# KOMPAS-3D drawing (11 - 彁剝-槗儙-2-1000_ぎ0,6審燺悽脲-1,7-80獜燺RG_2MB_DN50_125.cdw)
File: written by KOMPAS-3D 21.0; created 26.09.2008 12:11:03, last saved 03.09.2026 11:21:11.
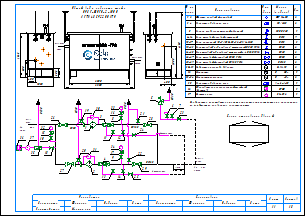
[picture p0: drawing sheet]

Sheets 1-2: A3, landscape

Document properties: Наименование: Макро:21; Автор: RaskoAdmin; Форматы листов документа: 2xA3; Полное имя файла: \\UR38nt01\Departments\КТО\КБ ПУРДГ\Заявки\Прайс-лист на типовые шкафы ГРПШ\ПРДГ_стандарт_20_03_2026\ПРДГ с RG_2MB\ПРДГ-ШУГО-2-1000_до0,6МПа_Рвых-1,7-80кПа_RG_2MB_DN50_125.cdw

Title block, sheet 1: Наименование: Пункт учета газа / ПУГ-Ш-400-Р / ЛГТИ.485922.001ТУ; designation: ЛГТИ.03.4411141; sheet number: 1; Количество листов документа: 2; organisation: ООО "ЭЛЬСТЕР Газэлектроника"; Форматы листов документа: A3; stored path: C:\Рабочие документы\Компас\ПУГ\Схема.cdw; Разработал: Устинов; Проверил: Кошкин; Утвердил: Кошкин
Title block, sheet 2: sheet number: 2; stored path: D:\Рабочие документы\Заявки\ПУРДГ\ПУРДГ-ШУЭО-2-100-Р 4411220.cdw; designation, second copy: ЛГТИ.03.4411141-

Views: Вид 1, Вид 2
Referenced files: wcvoit.frw
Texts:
  Normal
  Вход
  газа
  PDI
  Выход
  Р=     кПа
  DN125
  DN50
  DN20
  Импульс DN20
  ≥5DN
  HYSWLongFangSong
  Общий вид и габариты шкафа
  ПРДГ-ШУГО-2-1000
  Выход газа
  Вход газа
  Р=        МПа
  logo-rasko-ge.png
  № на
  схеме
  Усл.
  обозн.
  Марка
  (модель)
  Кол.
  Фильтр газовый фланцевый
  ФГ 16-50
  Регулятор давления газа
  RG/2MB
  Клапан предохранительный сбросной
  КПС DN20
  Кран шаровой газовый латунный
  DN15
  Кран кнопочный VE-РАСКО-НЗ-1,6-G1/2-М20
  Кран шаровой "под приварку" штуцерный DN20 PN16
  Кран шаровой "под приварку" штуцерный п/п DN20 PN16
  Кран шаровой фланцевый DN50 PN16
  Кран шаровой фланцевый DN125 PN16
  Индикатор перепада давления
  Delta 15
  Манометр
  Манометр-напоромер
  0...     МПа
  0...     кПа
  Обогреватель газогорелочный шкафной
  (Эльтон")
  Счетчик газа
  Venio-A-15
  ОГШН
  BK-G1,6
  Схема открывания дверей
  Предприятие изготовитель может заменять комплектующие на аналогичные,
  не ухудшающие заявленных характеристик.
  Должность
  Конструктор
  Фамилия
  Подпись
  Дата
  Согласовано
  Максимкин
  Лист
  Листов
  POLYLINE_STYLE_0.18_RGB_0_0_0
  POLYLINE_STYLE_0.50_RGB_0_0_0
  POLYLINE_STYLE_0.34_RGB_0_0_0
  PHANTOM_RGB_0_0_0_SC_1_THICK_0.18
  K5LT_THIN_RGB_0_0_0_THICK_0.18
  K5LT32769_RGB_0_0_0_THICK_0.18
  K5LT12_RGB_0_0_0_SC_1_THICK_0.18
  K5LT_DASHED_RGB_0_0_0_SC_1_THICK_0.18
  ACISOTGL_RGB_0_0_0_SC_0.8_THICK_0.25
  CONTINUOUS_RGB_0_127_31_THICK_0.3
  CONTINUOUS_RGB_0_0_255_THICK_0.35
  CONTINUOUS_RGB_255_0_0_THICK_0.35
  POLYLINE_STYLE_0.25_RGB_0_0_0
  CONTINUOUS_RGB_0_0_0_THICK_0.5
  POLYLINE_STYLE_0.35_RGB_0_0_255
  CONTINUOUS_RGB_0_0_0_THICK_0.4
  CONTINUOUS_RGB_0_0_0_THICK_0.35
  Без оформления
Dimensions and other numbers on the sheet: 1; 2; 3; 4; 5; 10; 27; 28; 29; 23; 8; 12; 19; 20; 21; 22; 25; 24; 30; 31; 15; 16; 26; 6; 7; 11; 14; 13; 33; 400; 1050; 500; 305; 2500; 1565; 32; 2800; 9; 17; 34; 1000; 4130; 1, 2; 3, 4; 6-14; 15-17; 18-23; 24-25; 26-27; 28-29; 30-31; 33-34; 35; 36; 37; 18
